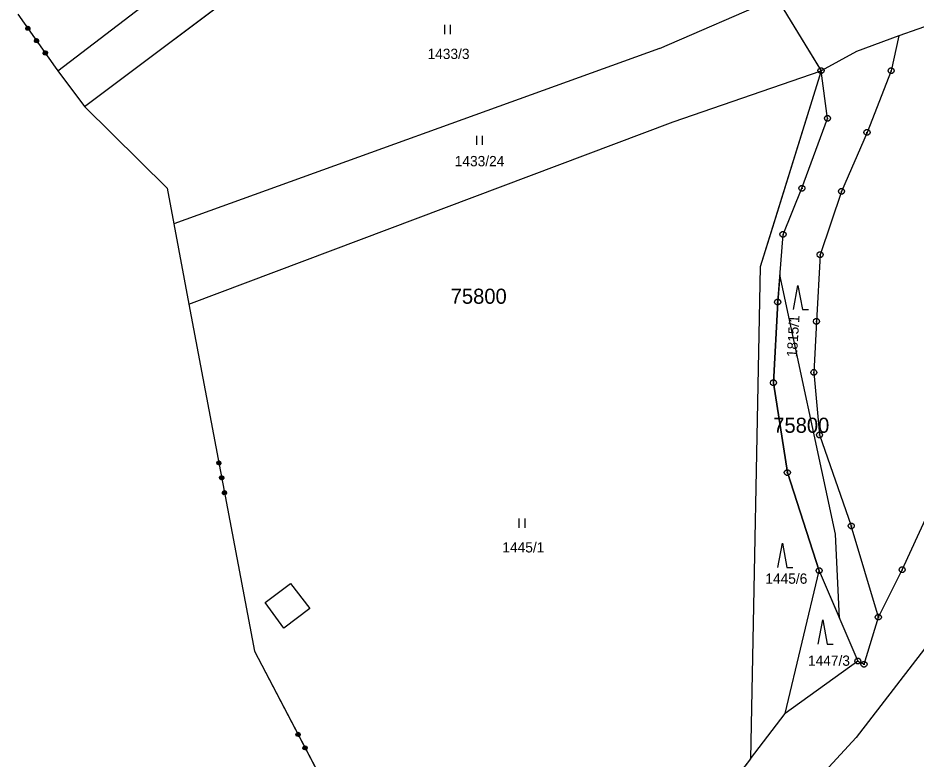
# Model space of a CAD drawing. Extents: x -779618 to -776429, y -1144546 to -1143350.
# Drawn here: x -779404.6 to -779255.7, y -1144283.6 to -1144160.9 of the extents above; entities that cross this region are included whole.
import ezdxf

# ---------------------------------------------------------------- set-up
doc = ezdxf.new("R2010")
doc.units = 0
for name, color, linetype in [('1', 7, 'Continuous'), ('11', 7, 'Continuous'), ('2', 7, 'Continuous'), ('3', 7, 'Continuous'), ('4', 7, 'Continuous'), ('6', 7, 'Continuous'), ('8', 7, 'Continuous')]:
    doc.layers.add(name, color=color, linetype=linetype)

msp = doc.modelspace()

# ---------------------------------------------------------------- linework, layer by layer
at = {"layer": '1'}
for p, q in [((-779393.54, -1144175.59), (-779363.98, -1144153.41)), ((-779298.22, -1144165.96), (-779278.85, -1144157.52)), ((-779278.85, -1144157.52), (-779271.48, -1144169.65)), ((-779404.55, -1144160.27), (-779398.38, -1144169.05)), ((-779251.94, -1144161.56), (-779258.57, -1144163.89)), ((-779258.57, -1144163.89), (-779265.62, -1144166.46)), ((-779258.57, -1144163.89), (-779259.86, -1144169.66)), ((-779298.22, -1144165.96), (-779378.71, -1144195.02)), ((-779265.62, -1144166.46), (-779271.48, -1144169.65)), ((-779398.38, -1144169.05), (-779397.92, -1144169.67)), ((-779397.92, -1144169.67), (-779393.54, -1144175.59)), ((-779295.98, -1144178.13), (-779271.48, -1144169.65)), ((-779271.48, -1144169.65), (-779281.54, -1144202.11)), ((-779270.41, -1144177.54), (-779271.48, -1144169.65)), ((-779259.86, -1144169.66), (-779263.86, -1144179.87)), ((-779393.54, -1144175.59), (-779379.81, -1144189.09)), ((-779376.24, -1144208.33), (-779295.98, -1144178.13)), ((-779274.64, -1144189.12), (-779270.41, -1144177.54)), ((-779263.86, -1144179.87), (-779268.08, -1144189.63)), ((-779379.81, -1144189.09), (-779378.71, -1144195.02)), ((-779277.77, -1144196.75), (-779274.64, -1144189.12)), ((-779268.08, -1144189.63), (-779271.63, -1144200.12)), ((-779378.71, -1144195.02), (-779376.24, -1144208.33)), ((-779278.66, -1144207.98), (-779277.77, -1144196.75)), ((-779271.63, -1144200.12), (-779272.24, -1144211.17)), ((-779281.54, -1144202.11), (-779283.19, -1144283.63)), ((-779376.24, -1144208.33), (-779365.36, -1144265.8)), ((-779279.36, -1144221.34), (-779278.66, -1144207.98)), ((-779258.02, -1144252.3), (-779237.84, -1144208.3)), ((-779272.24, -1144211.17), (-779272.67, -1144219.63)), ((-779272.67, -1144219.63), (-779271.73, -1144229.98)), ((-779277.06, -1144236.21), (-779279.36, -1144221.34)), ((-779271.73, -1144229.98), (-779266.46, -1144245.04)), ((-779271.79, -1144252.46), (-779277.06, -1144236.21)), ((-779261.98, -1144260.16), (-779266.46, -1144245.04)), ((-779277.43, -1144276.1), (-779271.79, -1144252.46)), ((-779271.79, -1144252.46), (-779265.38, -1144267.43)), ((-779261.98, -1144260.16), (-779258.02, -1144252.3)), ((-779264.35, -1144267.95), (-779261.98, -1144260.16)), ((-779365.36, -1144265.8), (-779348.59, -1144297.78)), ((-779265.38, -1144267.43), (-779277.43, -1144276.1)), ((-779265.38, -1144267.43), (-779264.35, -1144267.95)), ((-779283.19, -1144283.63), (-779277.43, -1144276.1)), ((-779283.19, -1144283.63), (-779292.3, -1144295.43))]:
    msp.add_line(p, q, dxfattribs=at)
for points in [[(-779402.57, -1144162.54), (-779402.61, -1144162.8), (-779402.83, -1144162.96), (-779403.1, -1144162.91), (-779403.25, -1144162.69), (-779403.21, -1144162.43), (-779402.99, -1144162.27), (-779402.72, -1144162.32), (-779402.57, -1144162.54), (-779402.59, -1144162.57), (-779402.73, -1144162.37), (-779402.84, -1144162.35), (-779402.61, -1144162.68), (-779402.64, -1144162.77), (-779402.95, -1144162.33), (-779403.02, -1144162.38), (-779402.71, -1144162.81), (-779402.77, -1144162.87), (-779403.08, -1144162.43), (-779403.14, -1144162.48), (-779402.84, -1144162.91), (-779402.93, -1144162.92), (-779403.18, -1144162.57), (-779403.21, -1144162.67), (-779403.05, -1144162.9)], [(-779401.12, -1144164.59), (-779401.17, -1144164.86), (-779401.39, -1144165.01), (-779401.65, -1144164.96), (-779401.81, -1144164.74), (-779401.76, -1144164.48), (-779401.54, -1144164.32), (-779401.28, -1144164.37), (-779401.12, -1144164.59), (-779401.16, -1144164.61), (-779401.3, -1144164.41), (-779401.41, -1144164.39), (-779401.18, -1144164.72), (-779401.2, -1144164.83), (-779401.52, -1144164.37), (-779401.59, -1144164.42), (-779401.27, -1144164.87), (-779401.33, -1144164.92), (-779401.65, -1144164.46), (-779401.72, -1144164.51), (-779401.4, -1144164.97), (-779401.51, -1144164.95), (-779401.74, -1144164.62), (-779401.76, -1144164.73), (-779401.62, -1144164.93)], [(-779399.68, -1144166.64), (-779399.73, -1144166.91), (-779399.95, -1144167.06), (-779400.21, -1144167.02), (-779400.37, -1144166.8), (-779400.32, -1144166.53), (-779400.1, -1144166.38), (-779399.83, -1144166.42), (-779399.68, -1144166.64), (-779399.74, -1144166.63), (-779399.87, -1144166.44), (-779399.97, -1144166.43), (-779399.75, -1144166.75), (-779399.77, -1144166.86), (-779400.07, -1144166.43), (-779400.14, -1144166.48), (-779399.84, -1144166.9), (-779399.9, -1144166.95), (-779400.2, -1144166.52), (-779400.28, -1144166.56), (-779399.98, -1144166.99), (-779400.06, -1144167), (-779400.3, -1144166.66), (-779400.34, -1144166.75), (-779400.2, -1144166.95)], [(-779370.93, -1144234.68), (-779371.08, -1144234.9), (-779371.34, -1144234.95), (-779371.56, -1144234.8), (-779371.61, -1144234.53), (-779371.46, -1144234.31), (-779371.2, -1144234.26), (-779370.98, -1144234.41), (-779370.93, -1144234.68), (-779370.96, -1144234.69), (-779371.01, -1144234.46), (-779371.1, -1144234.39), (-779371.03, -1144234.79), (-779371.09, -1144234.86), (-779371.19, -1144234.33), (-779371.27, -1144234.35), (-779371.17, -1144234.87), (-779371.25, -1144234.89), (-779371.35, -1144234.37), (-779371.43, -1144234.39), (-779371.33, -1144234.91), (-779371.42, -1144234.87), (-779371.5, -1144234.45), (-779371.56, -1144234.53), (-779371.51, -1144234.81)], [(-779370.46, -1144237.14), (-779370.61, -1144237.37), (-779370.88, -1144237.42), (-779371.1, -1144237.26), (-779371.15, -1144237), (-779371, -1144236.78), (-779370.73, -1144236.73), (-779370.51, -1144236.88), (-779370.46, -1144237.14), (-779370.5, -1144237.14), (-779370.55, -1144236.9), (-779370.64, -1144236.84), (-779370.56, -1144237.23), (-779370.63, -1144237.33), (-779370.73, -1144236.78), (-779370.81, -1144236.79), (-779370.71, -1144237.34), (-779370.79, -1144237.36), (-779370.89, -1144236.81), (-779370.97, -1144236.82), (-779370.86, -1144237.37), (-779370.96, -1144237.31), (-779371.03, -1144236.92), (-779371.1, -1144237.01), (-779371.05, -1144237.24)], [(-779369.99, -1144239.61), (-779370.15, -1144239.83), (-779370.41, -1144239.88), (-779370.63, -1144239.73), (-779370.68, -1144239.46), (-779370.53, -1144239.24), (-779370.27, -1144239.19), (-779370.04, -1144239.34), (-779369.99, -1144239.61), (-779370.04, -1144239.58), (-779370.09, -1144239.34), (-779370.17, -1144239.3), (-779370.1, -1144239.67), (-779370.17, -1144239.76), (-779370.26, -1144239.25), (-779370.34, -1144239.27), (-779370.25, -1144239.78), (-779370.33, -1144239.79), (-779370.42, -1144239.28), (-779370.5, -1144239.29), (-779370.41, -1144239.8), (-779370.49, -1144239.77), (-779370.57, -1144239.37), (-779370.64, -1144239.44), (-779370.59, -1144239.67)], [(-779357.79, -1144279.54), (-779357.87, -1144279.8), (-779358.11, -1144279.92), (-779358.37, -1144279.84), (-779358.49, -1144279.6), (-779358.41, -1144279.35), (-779358.17, -1144279.22), (-779357.92, -1144279.3), (-779357.79, -1144279.54), (-779357.82, -1144279.57), (-779357.93, -1144279.36), (-779358.04, -1144279.32), (-779357.86, -1144279.68), (-779357.9, -1144279.77), (-779358.15, -1144279.29), (-779358.22, -1144279.33), (-779357.97, -1144279.8), (-779358.04, -1144279.84), (-779358.29, -1144279.37), (-779358.36, -1144279.41), (-779358.11, -1144279.88), (-779358.21, -1144279.87), (-779358.41, -1144279.49), (-779358.44, -1144279.59), (-779358.31, -1144279.84)], [(-779356.63, -1144281.77), (-779356.71, -1144282.02), (-779356.95, -1144282.15), (-779357.2, -1144282.07), (-779357.33, -1144281.83), (-779357.25, -1144281.57), (-779357.01, -1144281.45), (-779356.75, -1144281.53), (-779356.63, -1144281.77), (-779356.67, -1144281.78), (-779356.78, -1144281.56), (-779356.89, -1144281.53), (-779356.7, -1144281.88), (-779356.73, -1144281.99), (-779356.99, -1144281.5), (-779357.06, -1144281.53), (-779356.8, -1144282.03), (-779356.88, -1144282.07), (-779357.14, -1144281.57), (-779357.21, -1144281.61), (-779356.95, -1144282.1), (-779357.05, -1144282.07), (-779357.24, -1144281.71), (-779357.27, -1144281.82), (-779357.16, -1144282.04)]]:
    msp.add_lwpolyline(points, dxfattribs=at)
at = {"layer": '11'}
for points in [[(-779393.54, -1144175.59), (-779363.98, -1144153.41), (-779349.51, -1144142.56), (-779304.36, -1144115.54), (-779295.74, -1144129.72), (-779278.85, -1144157.52), (-779271.57, -1144169.5), (-779271.48, -1144169.65), (-779279.8, -1144196.5), (-779281.54, -1144202.11), (-779283.19, -1144283.63), (-779292.3, -1144295.43), (-779329.76, -1144324.23)], [(-779393.54, -1144175.59), (-779379.81, -1144189.09), (-779378.71, -1144195.02), (-779376.24, -1144208.33), (-779365.36, -1144265.8), (-779348.59, -1144297.78), (-779329.76, -1144324.23)]]:
    msp.add_lwpolyline(points, dxfattribs=at)
msp.add_lwpolyline([(-779271.79, -1144252.46), (-779268.43, -1144260.3), (-779269.06, -1144246.4), (-779278.3, -1144203.46), (-779278.66, -1144207.98), (-779279.36, -1144221.34), (-779277.06, -1144236.21)], close=True, dxfattribs=at)
at = {"layer": '3'}
for p, q in [((-779333.88, -1144162.07), (-779333.88, -1144163.57)), ((-779332.88, -1144163.57), (-779332.88, -1144162.07)), ((-779328.56, -1144180.44), (-779328.56, -1144181.94)), ((-779327.56, -1144181.94), (-779327.56, -1144180.44)), ((-779321.53, -1144243.84), (-779321.53, -1144245.34)), ((-779320.53, -1144245.34), (-779320.53, -1144243.84))]:
    msp.add_line(p, q, dxfattribs=at)
for points in [[(-779276.06, -1144209.2), (-779275.31, -1144205.2), (-779274.56, -1144209.2), (-779273.56, -1144209.2)], [(-779278.63, -1144251.92), (-779277.88, -1144247.92), (-779277.13, -1144251.92), (-779276.13, -1144251.92)], [(-779271.95, -1144264.61), (-779271.2, -1144260.61), (-779270.45, -1144264.61), (-779269.45, -1144264.61)]]:
    msp.add_lwpolyline(points, dxfattribs=at)
at = {"layer": '4'}
for p, q in [((-779397.92, -1144169.67), (-779364.4, -1144143.94)), ((-779363.56, -1144257.75), (-779359.4, -1144254.57)), ((-779359.4, -1144254.57), (-779356.21, -1144258.73)), ((-779360.5, -1144261.97), (-779363.56, -1144257.75)), ((-779356.21, -1144258.73), (-779360.5, -1144261.97))]:
    msp.add_line(p, q, dxfattribs=at)
at = {"layer": '6'}
for p, q in [((-779250.95, -1144260.96), (-779265.64, -1144280.11)), ((-779265.64, -1144280.11), (-779285.51, -1144301.4))]:
    msp.add_line(p, q, dxfattribs=at)
at = {"layer": '8'}
for p, q in [((-779271.6, -1144169.65), (-779271.36, -1144169.65)), ((-779259.98, -1144169.66), (-779259.74, -1144169.66)), ((-779270.53, -1144177.54), (-779270.29, -1144177.54)), ((-779263.98, -1144179.87), (-779263.74, -1144179.87)), ((-779274.76, -1144189.12), (-779274.52, -1144189.12)), ((-779268.2, -1144189.63), (-779267.96, -1144189.63)), ((-779277.89, -1144196.75), (-779277.65, -1144196.75)), ((-779271.75, -1144200.12), (-779271.51, -1144200.12)), ((-779278.78, -1144207.98), (-779278.54, -1144207.98)), ((-779272.36, -1144211.17), (-779272.12, -1144211.17)), ((-779272.79, -1144219.63), (-779272.55, -1144219.63)), ((-779279.48, -1144221.34), (-779279.24, -1144221.34)), ((-779271.85, -1144229.98), (-779271.61, -1144229.98)), ((-779277.18, -1144236.21), (-779276.94, -1144236.21)), ((-779266.58, -1144245.04), (-779266.34, -1144245.04)), ((-779271.91, -1144252.46), (-779271.67, -1144252.46)), ((-779258.14, -1144252.3), (-779257.9, -1144252.3)), ((-779262.1, -1144260.16), (-779261.86, -1144260.16)), ((-779265.5, -1144267.43), (-779265.26, -1144267.43)), ((-779264.47, -1144267.95), (-779264.23, -1144267.95))]:
    msp.add_line(p, q, dxfattribs=at)
for points in [[(-779271.33, -1144169.17), (-779271.08, -1144169.35), (-779270.98, -1144169.64), (-779271.08, -1144169.93), (-779271.33, -1144170.11), (-779271.64, -1144170.11), (-779271.89, -1144169.93), (-779271.99, -1144169.64), (-779271.89, -1144169.35), (-779271.64, -1144169.17)], [(-779259.71, -1144169.18), (-779259.46, -1144169.36), (-779259.36, -1144169.65), (-779259.46, -1144169.94), (-779259.71, -1144170.12), (-779260.02, -1144170.12), (-779260.27, -1144169.94), (-779260.37, -1144169.65), (-779260.27, -1144169.36), (-779260.02, -1144169.18)], [(-779270.26, -1144177.06), (-779270.01, -1144177.24), (-779269.91, -1144177.53), (-779270.01, -1144177.82), (-779270.26, -1144178), (-779270.57, -1144178), (-779270.82, -1144177.82), (-779270.92, -1144177.53), (-779270.82, -1144177.24), (-779270.57, -1144177.06)], [(-779263.71, -1144179.39), (-779263.46, -1144179.57), (-779263.36, -1144179.86), (-779263.46, -1144180.15), (-779263.71, -1144180.33), (-779264.02, -1144180.33), (-779264.27, -1144180.15), (-779264.37, -1144179.86), (-779264.27, -1144179.57), (-779264.02, -1144179.39)], [(-779274.49, -1144188.64), (-779274.24, -1144188.82), (-779274.14, -1144189.11), (-779274.24, -1144189.4), (-779274.49, -1144189.58), (-779274.8, -1144189.58), (-779275.05, -1144189.4), (-779275.15, -1144189.11), (-779275.05, -1144188.82), (-779274.8, -1144188.64)], [(-779267.93, -1144189.15), (-779267.68, -1144189.33), (-779267.58, -1144189.62), (-779267.68, -1144189.91), (-779267.93, -1144190.09), (-779268.24, -1144190.09), (-779268.49, -1144189.91), (-779268.59, -1144189.62), (-779268.49, -1144189.33), (-779268.24, -1144189.15)], [(-779277.62, -1144196.27), (-779277.37, -1144196.45), (-779277.27, -1144196.74), (-779277.37, -1144197.03), (-779277.62, -1144197.21), (-779277.93, -1144197.21), (-779278.18, -1144197.03), (-779278.28, -1144196.74), (-779278.18, -1144196.45), (-779277.93, -1144196.27)], [(-779271.48, -1144199.64), (-779271.23, -1144199.82), (-779271.13, -1144200.11), (-779271.23, -1144200.4), (-779271.48, -1144200.58), (-779271.79, -1144200.58), (-779272.04, -1144200.4), (-779272.14, -1144200.11), (-779272.04, -1144199.82), (-779271.79, -1144199.64)], [(-779278.51, -1144207.5), (-779278.26, -1144207.68), (-779278.16, -1144207.97), (-779278.26, -1144208.26), (-779278.51, -1144208.44), (-779278.82, -1144208.44), (-779279.07, -1144208.26), (-779279.17, -1144207.97), (-779279.07, -1144207.68), (-779278.82, -1144207.5)], [(-779272.09, -1144210.69), (-779271.84, -1144210.87), (-779271.74, -1144211.16), (-779271.84, -1144211.45), (-779272.09, -1144211.63), (-779272.4, -1144211.63), (-779272.65, -1144211.45), (-779272.75, -1144211.16), (-779272.65, -1144210.87), (-779272.4, -1144210.69)], [(-779272.52, -1144219.15), (-779272.27, -1144219.33), (-779272.17, -1144219.62), (-779272.27, -1144219.91), (-779272.52, -1144220.09), (-779272.83, -1144220.09), (-779273.08, -1144219.91), (-779273.18, -1144219.62), (-779273.08, -1144219.33), (-779272.83, -1144219.15)], [(-779279.21, -1144220.86), (-779278.96, -1144221.04), (-779278.86, -1144221.33), (-779278.96, -1144221.62), (-779279.21, -1144221.8), (-779279.52, -1144221.8), (-779279.77, -1144221.62), (-779279.87, -1144221.33), (-779279.77, -1144221.04), (-779279.52, -1144220.86)], [(-779271.58, -1144229.5), (-779271.33, -1144229.68), (-779271.23, -1144229.97), (-779271.33, -1144230.26), (-779271.58, -1144230.44), (-779271.89, -1144230.44), (-779272.14, -1144230.26), (-779272.24, -1144229.97), (-779272.14, -1144229.68), (-779271.89, -1144229.5)], [(-779276.91, -1144235.73), (-779276.66, -1144235.91), (-779276.56, -1144236.2), (-779276.66, -1144236.49), (-779276.91, -1144236.67), (-779277.22, -1144236.67), (-779277.47, -1144236.49), (-779277.57, -1144236.2), (-779277.47, -1144235.91), (-779277.22, -1144235.73)], [(-779266.31, -1144244.56), (-779266.06, -1144244.74), (-779265.96, -1144245.03), (-779266.06, -1144245.32), (-779266.31, -1144245.5), (-779266.62, -1144245.5), (-779266.87, -1144245.32), (-779266.97, -1144245.03), (-779266.87, -1144244.74), (-779266.62, -1144244.56)], [(-779257.87, -1144251.82), (-779257.62, -1144252), (-779257.52, -1144252.29), (-779257.62, -1144252.58), (-779257.87, -1144252.76), (-779258.18, -1144252.76), (-779258.43, -1144252.58), (-779258.53, -1144252.29), (-779258.43, -1144252), (-779258.18, -1144251.82)], [(-779271.64, -1144251.98), (-779271.39, -1144252.16), (-779271.29, -1144252.45), (-779271.39, -1144252.74), (-779271.64, -1144252.92), (-779271.95, -1144252.92), (-779272.2, -1144252.74), (-779272.3, -1144252.45), (-779272.2, -1144252.16), (-779271.95, -1144251.98)], [(-779261.83, -1144259.68), (-779261.58, -1144259.86), (-779261.48, -1144260.15), (-779261.58, -1144260.44), (-779261.83, -1144260.62), (-779262.14, -1144260.62), (-779262.39, -1144260.44), (-779262.49, -1144260.15), (-779262.39, -1144259.86), (-779262.14, -1144259.68)], [(-779265.23, -1144266.95), (-779264.98, -1144267.13), (-779264.88, -1144267.42), (-779264.98, -1144267.71), (-779265.23, -1144267.89), (-779265.54, -1144267.89), (-779265.79, -1144267.71), (-779265.89, -1144267.42), (-779265.79, -1144267.13), (-779265.54, -1144266.95)], [(-779264.2, -1144267.47), (-779263.95, -1144267.65), (-779263.85, -1144267.94), (-779263.95, -1144268.23), (-779264.2, -1144268.41), (-779264.51, -1144268.41), (-779264.76, -1144268.23), (-779264.86, -1144267.94), (-779264.76, -1144267.65), (-779264.51, -1144267.47)]]:
    msp.add_lwpolyline(points, close=True, dxfattribs=at)

# ---------------------------------------------------------------- texts
at = {"layer": '11'}
for p in [(-779332.85, -1144208.25), (-779279.4, -1144229.62)]:
    msp.add_text('75800', height=2.5, dxfattribs=at).set_placement(p)
at = {"layer": '2'}
for s, p in [('1433/3', (-779336.68, -1144167.71)), ('1433/24', (-779332.17, -1144185.47)), ('1445/1', (-779324.28, -1144249.44)), ('1445/6', (-779280.7, -1144254.62)), ('1447/3', (-779273.64, -1144268.21))]:
    msp.add_text(s, height=1.7, dxfattribs=at).set_placement(p)
msp.add_text('1815/1', height=1.7, rotation=86.1729, dxfattribs=at).set_placement((-779275.49, -1144217.14))

doc.saveas('drawing.dxf')
